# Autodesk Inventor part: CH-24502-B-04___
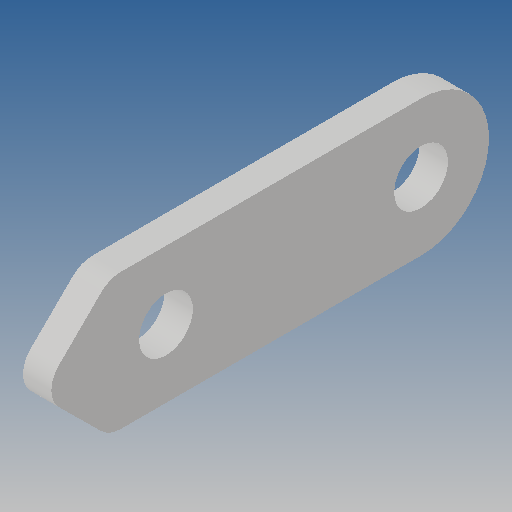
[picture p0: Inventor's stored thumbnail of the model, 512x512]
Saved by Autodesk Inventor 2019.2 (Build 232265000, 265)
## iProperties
Created: 2010-06
Part Number: CH-24502-B-04___
Material: Ogólny
Document SubType Name: Modeling
Designer: CADENGINEERING4
Density: 1 g/cm^3
Appearance: Domyślna
Author: CADENGINEERING4
Revision Number: ANY
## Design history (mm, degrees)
feature "NONE"
node "Bryła1"
